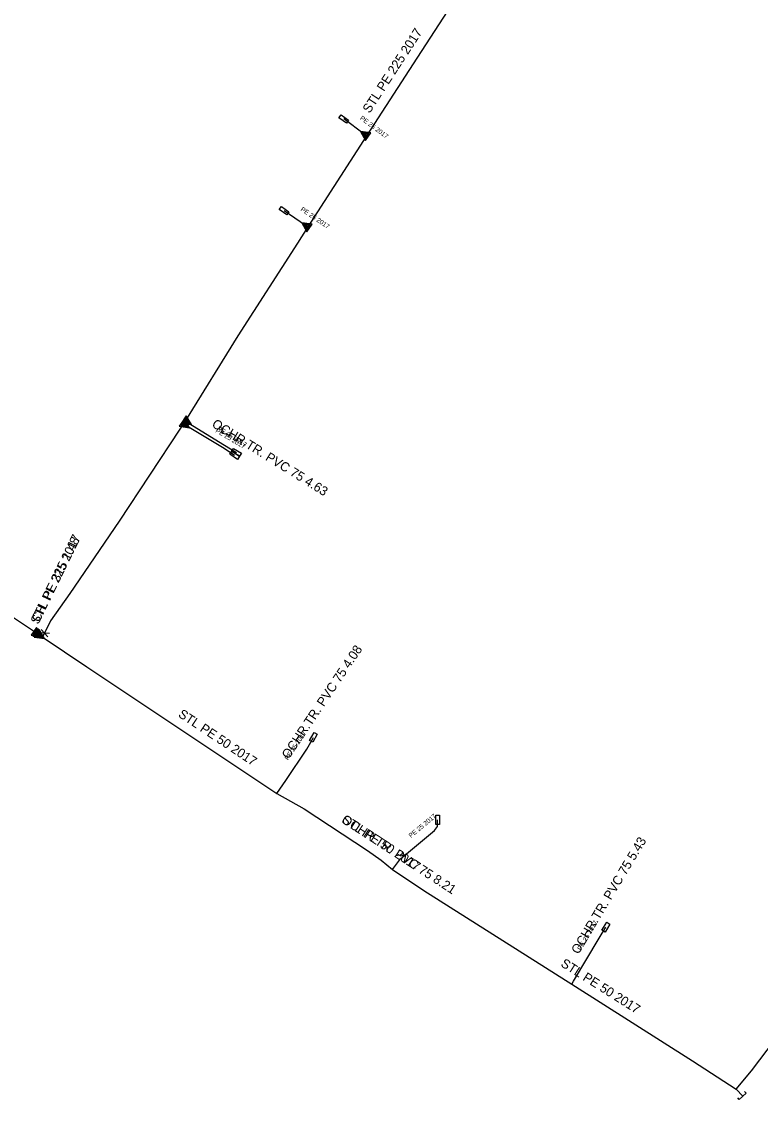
# Model space of a CAD drawing. Extents: x -742724 to -742460, y -1054602 to -1054379.
# Drawn here: x -742616.2 to -742536.2, y -1054602.3 to -1054485.6 of the extents above; entities that cross this region are included whole.
import ezdxf

# ---------------------------------------------------------------- set-up
doc = ezdxf.new("R2010")
doc.units = 0
for name, color, linetype in [('ST OP Chráni_ka - provoz', 7, 'Continuous'), ('ST Úsek p_ípojky - provoz', 7, 'Continuous'), ('ST Úsek plynovodu - provoz', 7, 'Continuous'), ('Vrstva 1', 7, 'Continuous')]:
    doc.layers.add(name, color=color, linetype=linetype)

msp = doc.modelspace()

# ---------------------------------------------------------------- linework, layer by layer
at = {"layer": 'ST OP Chráni_ka - provoz'}
for points in [[(-742598.44, -1054529.34), (-742594.3, -1054531.81)], [(-742598.19, -1054529.07), (-742594.26, -1054531.51)], [(-742613.09, -1054550.51), (-742613.74, -1054551.84)], [(-742587.6, -1054567.81), (-742585.33, -1054564.42)], [(-742585.64, -1054570.89), (-742578.77, -1054575.37)], [(-742575.2, -1054576.3), (-742571.5, -1054573.23)], [(-742556.44, -1054589.53), (-742553.66, -1054584.87)]]:
    msp.add_lwpolyline(points, dxfattribs=at)
at = {"layer": 'ST Úsek p_ípojky - provoz'}
for points in [[(-742579.12, -1054497.81), (-742581.33, -1054496.16)], [(-742578.87, -1054497.98), (-742579.12, -1054497.81)], [(-742585.46, -1054507.69), (-742587.79, -1054506.11)], [(-742585.21, -1054507.86), (-742585.46, -1054507.69)], [(-742598.7, -1054529.16), (-742598.46, -1054529.32)], [(-742598.49, -1054528.84), (-742598.25, -1054529)], [(-742598.46, -1054529.32), (-742598.44, -1054529.34), (-742594.3, -1054531.81), (-742593.15, -1054532.58)], [(-742598.25, -1054529), (-742598.19, -1054529.07), (-742594.26, -1054531.51), (-742592.95, -1054532.27)], [(-742538.85, -1054601.24), (-742537.17, -1054599.24), (-742525.86, -1054584.33), (-742511.65, -1054566.49), (-742501.74, -1054553.54), (-742495.36, -1054545.45)], [(-742588.58, -1054569.2), (-742587.6, -1054567.81), (-742585.33, -1054564.42), (-742584.61, -1054563.14)], [(-742576.07, -1054577.44), (-742575.2, -1054576.3), (-742571.5, -1054573.23), (-742571.19, -1054572.78), (-742571.17, -1054572.06)], [(-742556.64, -1054589.86), (-742556.44, -1054589.53), (-742553.66, -1054584.87), (-742552.94, -1054583.69)]]:
    msp.add_lwpolyline(points, dxfattribs=at)
at = {"layer": 'ST Úsek plynovodu - provoz'}
for points in [[(-742542.79, -1054441.48), (-742547.74, -1054449.35), (-742550.94, -1054454.6), (-742551.56, -1054455.58), (-742558.62, -1054466.59), (-742566.91, -1054479.58), (-742570.05, -1054484.44), (-742573.42, -1054489.57), (-742578.87, -1054497.98), (-742585.21, -1054507.86), (-742586.36, -1054509.61), (-742592.8, -1054519.64), (-742598.49, -1054528.84), (-742598.7, -1054529.16), (-742599.1, -1054529.76), (-742605.67, -1054539.71), (-742611, -1054547.54), (-742613.09, -1054550.51)], [(-742614.49, -1054551.94), (-742621.13, -1054547.51), (-742621.72, -1054547.14), (-742631.67, -1054540.51), (-742639.51, -1054535.5), (-742641.78, -1054534.07), (-742645.9, -1054531.51)], [(-742613.09, -1054550.51), (-742613.74, -1054551.84), (-742614.01, -1054552.25)], [(-742614.31, -1054552.05), (-742614.49, -1054551.94)], [(-742614.18, -1054552.14), (-742614.31, -1054552.05)], [(-742614.01, -1054552.25), (-742614.18, -1054552.14)], [(-742614.01, -1054552.25), (-742609.16, -1054555.51), (-742588.58, -1054569.2), (-742585.64, -1054570.89)], [(-742585.64, -1054570.89), (-742578.77, -1054575.37)], [(-742578.77, -1054575.37), (-742577.3, -1054576.45), (-742576.07, -1054577.44), (-742572.66, -1054579.72), (-742556.64, -1054589.86), (-742543.55, -1054598.18), (-742538.85, -1054601.24), (-742538.13, -1054602)]]:
    msp.add_lwpolyline(points, dxfattribs=at)
at = {"layer": 'Vrstva 1'}
for p, q in [((-742613.38, -1054552.24), (-742614.1, -1054551.44)), ((-742613.2, -1054551.88), (-742614.28, -1054551.8))]:
    msp.add_line(p, q, dxfattribs=at)
for points in [[(-742581.85, -1054496.03), (-742581.61, -1054495.71), (-742580.81, -1054496.3), (-742581.05, -1054496.62)], [(-742578.98, -1054498.5), (-742578.42, -1054497.67), (-742579.53, -1054497.53)], [(-742578.6, -1054497.75), (-742579.35, -1054497.65), (-742578.98, -1054498.31)], [(-742579.16, -1054497.78), (-742578.97, -1054498.12), (-742578.77, -1054497.83)], [(-742588.32, -1054505.99), (-742588.09, -1054505.66), (-742587.27, -1054506.22), (-742587.49, -1054506.55)], [(-742585.32, -1054508.39), (-742584.76, -1054507.56), (-742585.87, -1054507.41)], [(-742584.94, -1054507.64), (-742585.69, -1054507.54), (-742585.32, -1054508.2)], [(-742585.5, -1054507.66), (-742585.31, -1054508.01), (-742585.11, -1054507.71)], [(-742598.59, -1054528.63), (-742599.16, -1054529.45), (-742598.05, -1054529.61)], [(-742598.98, -1054529.37), (-742598.24, -1054529.48), (-742598.6, -1054528.82)], [(-742598.4, -1054528.31), (-742598.94, -1054529.15), (-742597.83, -1054529.27)], [(-742598.42, -1054529.35), (-742598.61, -1054529.01), (-742598.81, -1054529.3)], [(-742598.77, -1054529.07), (-742598.01, -1054529.15), (-742598.4, -1054528.5)], [(-742598.2, -1054529.03), (-742598.41, -1054528.69), (-742598.6, -1054528.99)], [(-742592.63, -1054532.7), (-742592.85, -1054533.03), (-742593.68, -1054532.47), (-742593.45, -1054532.14)], [(-742592.42, -1054532.35), (-742592.62, -1054532.69), (-742593.48, -1054532.19), (-742593.28, -1054531.85)], [(-742614.62, -1054551.25), (-742615.18, -1054552.08), (-742614.07, -1054552.22)], [(-742614.46, -1054551.36), (-742615.01, -1054552.19), (-742613.9, -1054552.33)], [(-742615.01, -1054552), (-742614.26, -1054552.09), (-742614.63, -1054551.44)], [(-742614.32, -1054551.45), (-742614.87, -1054552.29), (-742613.76, -1054552.42)], [(-742614.83, -1054552.11), (-742614.08, -1054552.21), (-742614.46, -1054551.55)], [(-742614.44, -1054551.97), (-742614.64, -1054551.63), (-742614.83, -1054551.92)], [(-742614.69, -1054552.21), (-742613.94, -1054552.3), (-742614.32, -1054551.64)], [(-742614.27, -1054552.08), (-742614.47, -1054551.74), (-742614.66, -1054552.04)], [(-742614.13, -1054552.17), (-742614.33, -1054551.83), (-742614.52, -1054552.13)], [(-742584.55, -1054562.6), (-742584.2, -1054562.8), (-742584.68, -1054563.67), (-742585.03, -1054563.48)], [(-742571.36, -1054571.56), (-742570.96, -1054571.57), (-742570.98, -1054572.57), (-742571.38, -1054572.56)], [(-742552.85, -1054583.16), (-742552.51, -1054583.37), (-742553.03, -1054584.22), (-742553.37, -1054584.01)]]:
    msp.add_lwpolyline(points, close=True, dxfattribs=at)
msp.add_lwpolyline([(-742537.94, -1054601.48), (-742537.77, -1054601.66), (-742538.5, -1054602.35), (-742538.67, -1054602.16)], dxfattribs=at)

# ---------------------------------------------------------------- texts
at = {"layer": 'ST OP Chráni_ka - provoz'}
for s, rotation, p in [('OCHR.TR. PVC 75 4.63', 328.1494, (-742595.7, -1054529.44)), ('CH. PE 315 1.48', 63.9542, (-742614.31, -1054550.74)), ('OCHR.TR. PVC 75 4.08', 56.1931, (-742587.3, -1054565.56)), ('OCHR.TR. PVC 75 8.21', 326.8948, (-742581.66, -1054572.29)), ('OCHR.TR. PVC 75 5.43', 59.1811, (-742555.91, -1054586.69))]:
    msp.add_text(s, height=1, rotation=rotation, dxfattribs=at).set_placement(p)
at = {"layer": 'ST Úsek p_ípojky - provoz'}
for rotation, p in [(323.3963, (-742579.63, -1054496.18)), (325.8481, (-742586.06, -1054506.07)), (329.1789, (-742595.28, -1054530.06)), (328.1494, (-742595.09, -1054529.82)), (56.1931, (-742587.36, -1054565.66)), (39.6835, (-742574.05, -1054574.05)), (59.1811, (-742555.65, -1054586.26))]:
    msp.add_text('PE 25 2017', height=0.5, rotation=rotation, dxfattribs=at).set_placement(p)
at = {"layer": 'ST Úsek plynovodu - provoz'}
for s, rotation, p in [('STL PE 225 2017', 57.0224, (-742578.53, -1054495.62)), ('STL PE 225 2017', 63.9542, (-742614.42, -1054550.96)), ('STL PE 50 2017', 326.3575, (-742599.34, -1054560.84)), ('STL PE 50 2017', 326.8948, (-742581.66, -1054572.29)), ('STL PE 50 2017', 327.6778, (-742557.92, -1054587.86))]:
    msp.add_text(s, height=1, rotation=rotation, dxfattribs=at).set_placement(p)

doc.saveas('drawing.dxf')
